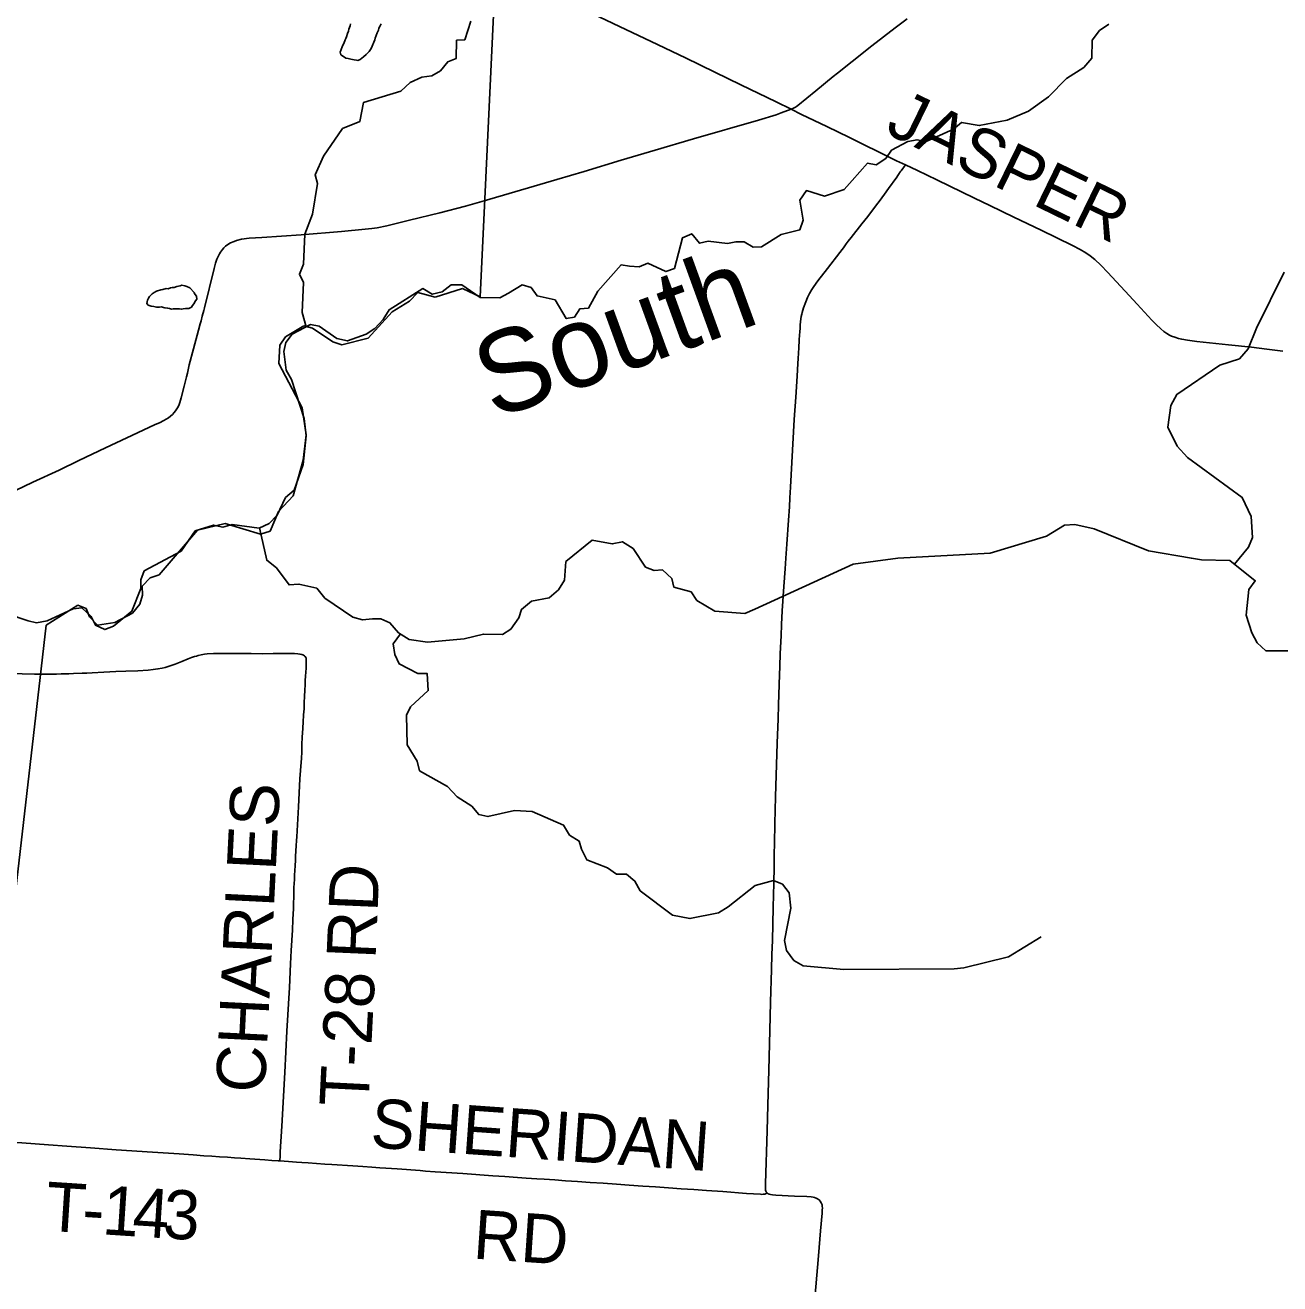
# Model space of a CAD drawing. Extents: x -49 to -8.2, y 9.4 to 23.5.
# Drawn here: x -13.706 to -12.98, y 11.259 to 11.988 of the extents above; entities that cross this region are included whole.
import ezdxf

# ---------------------------------------------------------------- set-up
doc = ezdxf.new("R2010")
doc.units = 0
for name, color, linetype in [('GM_X_County_Road', 7, 'Continuous'), ('GM_X_County_Road_Text', 7, 'Continuous'), ('GM_X_Minor_Lake', 7, 'Continuous'), ('GM_X_Minor_River', 7, 'Continuous'), ('GM_X_Minor_River_Text', 7, 'Continuous'), ('GM_X_Township', 7, 'Continuous'), ('GM_X_Township_Road', 7, 'Continuous'), ('GM_X_Township_Road_Text', 7, 'Continuous')]:
    doc.layers.add(name, color=color, linetype=linetype)

msp = doc.modelspace()

# ---------------------------------------------------------------- linework, layer by layer
at = {"layer": 'GM_X_County_Road'}
for points in [[(-13.41841, 12.01371), (-13.41025, 12.00973), (-13.40043, 12.0051), (-13.39281, 12.00159), (-13.36191, 11.98699), (-13.3437, 11.97825), (-13.32382, 11.9687), (-13.30675, 11.96046), (-13.29164, 11.95318), (-13.27121, 11.94332), (-13.26257, 11.93902)], [(-13.26257, 11.93902), (-13.26088, 11.93975), (-13.26007, 11.94021), (-13.25942, 11.94061), (-13.25876, 11.94112), (-13.24826, 11.94959), (-13.23823, 11.95794), (-13.23582, 11.9599), (-13.22726, 11.96658), (-13.21586, 11.97571), (-13.20237, 11.98618), (-13.19541, 11.99138)], [(-13.44022, 11.886), (-13.43699, 11.88691), (-13.41136, 11.89446), (-13.39827, 11.89841), (-13.38248, 11.90305), (-13.36105, 11.90947), (-13.34139, 11.91527), (-13.31905, 11.92185), (-13.28145, 11.93272), (-13.27135, 11.93587), (-13.26841, 11.93694), (-13.26257, 11.93902)], [(-13.26257, 11.93902), (-13.25657, 11.93593), (-13.24198, 11.92905), (-13.22888, 11.92263), (-13.21994, 11.91827), (-13.2124, 11.9146), (-13.20154, 11.90925), (-13.19644, 11.90684)], [(-13.27636, 11.31155), (-13.27668, 11.31183), (-13.27701, 11.31223), (-13.27729, 11.31272), (-13.27743, 11.31324), (-13.27752, 11.31393), (-13.2775, 11.31502), (-13.27743, 11.31717), (-13.27649, 11.34759), (-13.27609, 11.3625), (-13.27553, 11.38269), (-13.27494, 11.40567), (-13.27446, 11.42213), (-13.27398, 11.44107), (-13.27369, 11.44976), (-13.27344, 11.45783), (-13.27323, 11.46715), (-13.27302, 11.47709), (-13.2727, 11.49107), (-13.27248, 11.50038), (-13.27236, 11.50783), (-13.27224, 11.51404), (-13.27202, 11.52553), (-13.27162, 11.54105), (-13.27065, 11.5721), (-13.27016, 11.58607), (-13.26991, 11.59414), (-13.26949, 11.60594), (-13.26929, 11.61153), (-13.26911, 11.61649), (-13.26887, 11.62393), (-13.26845, 11.63416), (-13.26817, 11.64067), (-13.26771, 11.64873), (-13.26683, 11.66268), (-13.26604, 11.67289), (-13.26562, 11.6791), (-13.26504, 11.68715), (-13.26411, 11.70109), (-13.26363, 11.70883), (-13.26335, 11.71409), (-13.26303, 11.72029), (-13.26226, 11.73456), (-13.26076, 11.75937), (-13.25998, 11.77239), (-13.25917, 11.78448), (-13.25871, 11.79192), (-13.25853, 11.79471), (-13.25818, 11.80091), (-13.25789, 11.80524), (-13.25768, 11.80833), (-13.25759, 11.80988), (-13.25745, 11.81241), (-13.25729, 11.81421), (-13.25714, 11.81604), (-13.25695, 11.8176), (-13.25671, 11.81906), (-13.25646, 11.82048), (-13.25622, 11.82144), (-13.2559, 11.82262), (-13.25546, 11.82408), (-13.25418, 11.82754), (-13.25308, 11.83008), (-13.25199, 11.83228), (-13.25061, 11.83466), (-13.24943, 11.83644), (-13.24707, 11.83968), (-13.2416, 11.84682), (-13.23435, 11.85613), (-13.23306, 11.85786), (-13.23231, 11.85885), (-13.23066, 11.86109), (-13.22954, 11.86258), (-13.2278, 11.86476), (-13.22176, 11.87263), (-13.22, 11.8748), (-13.21828, 11.87699), (-13.2143, 11.88216), (-13.21244, 11.88464), (-13.21116, 11.8864), (-13.20768, 11.89117), (-13.20586, 11.89368), (-13.20457, 11.89542), (-13.20312, 11.89744), (-13.20184, 11.89918), (-13.20046, 11.90123), (-13.19942, 11.90274), (-13.19891, 11.90345), (-13.19644, 11.90684)], [(-13.19644, 11.90684), (-13.18947, 11.90355), (-13.1783, 11.89816), (-13.15637, 11.88749)], [(-13.72626, 11.71142), (-13.70153, 11.72307), (-13.68634, 11.73017), (-13.67485, 11.73567), (-13.65942, 11.74302), (-13.64089, 11.75176), (-13.63075, 11.75649), (-13.62819, 11.75757), (-13.62566, 11.75881), (-13.62431, 11.75961), (-13.62296, 11.76045), (-13.6218, 11.76134), (-13.62077, 11.76229), (-13.61978, 11.7634), (-13.61893, 11.76448), (-13.61813, 11.76566), (-13.61752, 11.76674), (-13.61694, 11.76809), (-13.6165, 11.76929), (-13.61562, 11.77198), (-13.61392, 11.77864), (-13.61262, 11.78408), (-13.61212, 11.78619), (-13.61098, 11.79102), (-13.60853, 11.80032), (-13.60563, 11.81111), (-13.60468, 11.81472), (-13.6042, 11.81651), (-13.60348, 11.8192), (-13.60259, 11.8225), (-13.60219, 11.824), (-13.59653, 11.84689), (-13.5958, 11.84987), (-13.59504, 11.85219), (-13.59418, 11.85413), (-13.59353, 11.85526), (-13.59292, 11.85619), (-13.59186, 11.85774), (-13.59096, 11.85876), (-13.58995, 11.85969), (-13.58815, 11.86104), (-13.58705, 11.86169), (-13.58506, 11.86254), (-13.58372, 11.86299), (-13.58075, 11.8638), (-13.57627, 11.86433), (-13.56908, 11.86479), (-13.54615, 11.86641), (-13.52295, 11.86826), (-13.50927, 11.8695), (-13.5053, 11.86997), (-13.50225, 11.87039), (-13.49674, 11.87144), (-13.4835, 11.87475), (-13.46603, 11.87904), (-13.45104, 11.88296), (-13.44022, 11.886)], [(-13.15637, 11.88749), (-13.1476, 11.88322), (-13.13362, 11.87645), (-13.11793, 11.86893), (-13.09975, 11.86011), (-13.09532, 11.85782), (-13.09208, 11.85589), (-13.08951, 11.8541), (-13.08683, 11.85194), (-13.08339, 11.84875), (-13.07925, 11.84451), (-13.06703, 11.83127), (-13.06237, 11.82626), (-13.05377, 11.81687), (-13.0514, 11.81444), (-13.04865, 11.81197), (-13.04687, 11.81042), (-13.04513, 11.80914), (-13.04362, 11.80831), (-13.04234, 11.8077), (-13.04053, 11.80702), (-13.03841, 11.80634), (-13.03647, 11.80589), (-13.03315, 11.80524), (-13.0277, 11.80453), (-13.00938, 11.80269), (-12.99609, 11.80129), (-12.98715, 11.80021), (-12.9779, 11.79897)], [(-13.24923, 11.24607), (-13.24684, 11.27518), (-13.24557, 11.28972), (-13.24464, 11.29992), (-13.24456, 11.30174), (-13.24449, 11.30294), (-13.24455, 11.30379), (-13.24473, 11.30472), (-13.24488, 11.3052), (-13.24525, 11.30601), (-13.24575, 11.30682), (-13.24645, 11.30758), (-13.24671, 11.30776), (-13.24734, 11.30818), (-13.24813, 11.30861), (-13.24902, 11.30894), (-13.24987, 11.30916), (-13.25094, 11.30936), (-13.25348, 11.30957), (-13.26065, 11.30983), (-13.27153, 11.31036), (-13.27337, 11.31054), (-13.27453, 11.31073), (-13.27535, 11.31099), (-13.27582, 11.31121), (-13.27628, 11.31148), (-13.27636, 11.31155)]]:
    msp.add_lwpolyline(points, dxfattribs=at)
at = {"layer": 'GM_X_Minor_Lake'}
for points in [[(-13.51769, 11.98838), (-13.51789, 11.98724), (-13.51828, 11.9863), (-13.51867, 11.98535), (-13.51887, 11.98422), (-13.51945, 11.98289), (-13.52004, 11.981), (-13.52043, 11.98005), (-13.52082, 11.97911), (-13.5216, 11.97703), (-13.52218, 11.97608), (-13.52257, 11.97514), (-13.52374, 11.97211), (-13.52319, 11.97059), (-13.52168, 11.96962), (-13.52036, 11.96866), (-13.51903, 11.96846), (-13.51752, 11.96806), (-13.51563, 11.96766), (-13.5143, 11.96746), (-13.51335, 11.96726), (-13.51202, 11.96781), (-13.51106, 11.96856), (-13.51011, 11.96931), (-13.50858, 11.97063), (-13.50781, 11.97157), (-13.50685, 11.97251), (-13.50569, 11.9742), (-13.50511, 11.97553), (-13.50414, 11.9778), (-13.50355, 11.97912), (-13.50335, 11.98026), (-13.50218, 11.98328), (-13.50141, 11.9848), (-13.50121, 11.98593), (-13.50043, 11.98725), (-13.49985, 11.98839)], [(-13.60812, 11.83284), (-13.61075, 11.83572), (-13.61245, 11.83631), (-13.61359, 11.8367), (-13.61529, 11.8371), (-13.61624, 11.83673), (-13.61719, 11.83655), (-13.61814, 11.83637), (-13.61967, 11.83581), (-13.62099, 11.83582), (-13.62195, 11.83564), (-13.62328, 11.83509), (-13.62442, 11.83529), (-13.62632, 11.83474), (-13.62746, 11.83456), (-13.62994, 11.83364), (-13.63127, 11.83289), (-13.63242, 11.83214), (-13.63395, 11.83064), (-13.63453, 11.8297), (-13.63511, 11.82857), (-13.63531, 11.82762), (-13.63551, 11.82648), (-13.63476, 11.82552), (-13.63306, 11.82494), (-13.63155, 11.82473), (-13.63003, 11.82452), (-13.62832, 11.82451), (-13.62718, 11.82469), (-13.6251, 11.82409), (-13.62359, 11.82389), (-13.62245, 11.82369), (-13.62132, 11.82329), (-13.62037, 11.82347), (-13.61904, 11.82346), (-13.6179, 11.82345), (-13.61657, 11.82344), (-13.61543, 11.82323), (-13.61448, 11.82341), (-13.61315, 11.82359), (-13.61125, 11.82376), (-13.60973, 11.8245), (-13.60915, 11.82545), (-13.60838, 11.82639), (-13.60741, 11.82809), (-13.60664, 11.82903), (-13.60682, 11.83074), (-13.60757, 11.8317), (-13.60812, 11.83265), (-13.60812, 11.83265), (-13.60812, 11.83284)]]:
    msp.add_lwpolyline(points, dxfattribs=at)
at = {"layer": 'GM_X_Minor_River'}
for points in [[(-13.54329, 11.8131), (-13.54574, 11.82144), (-13.5449, 11.8387), (-13.54729, 11.84348), (-13.54493, 11.84933), (-13.54409, 11.86677), (-13.53975, 11.87828), (-13.53682, 11.89608), (-13.53807, 11.90103), (-13.53336, 11.91178), (-13.5223, 11.92793), (-13.51219, 11.93195), (-13.51013, 11.94293), (-13.4886, 11.94943), (-13.48322, 11.95447), (-13.47634, 11.9576), (-13.47065, 11.95827), (-13.46567, 11.96123), (-13.46142, 11.96648), (-13.45646, 11.96849), (-13.4563, 11.97892), (-13.45155, 11.97923), (-13.44798, 11.98999)], [(-13.07867, 11.9882), (-13.08403, 11.98467), (-13.08829, 11.97904), (-13.08864, 11.96861), (-13.09327, 11.96318), (-13.10323, 11.95688), (-13.11363, 11.94622), (-13.12513, 11.93785), (-13.13753, 11.93273), (-13.1537, 11.92955), (-13.16391, 11.93142), (-13.16871, 11.9275), (-13.18436, 11.92034), (-13.18966, 11.92137), (-13.19498, 11.92031), (-13.20454, 11.91533), (-13.20784, 11.91045), (-13.21339, 11.90693), (-13.21849, 11.90776), (-13.22737, 11.89784), (-13.232, 11.8926), (-13.24324, 11.88878), (-13.25381, 11.89198), (-13.2575, 11.88634), (-13.25559, 11.87474), (-13.25757, 11.86926), (-13.26842, 11.86658), (-13.27972, 11.85935), (-13.28465, 11.85924), (-13.28972, 11.86235), (-13.29465, 11.86223), (-13.2994, 11.86136), (-13.31057, 11.86266), (-13.31571, 11.86141), (-13.32017, 11.86699), (-13.32552, 11.8646), (-13.33015, 11.84683), (-13.33511, 11.84501), (-13.34565, 11.84991), (-13.35062, 11.84771), (-13.35611, 11.84817), (-13.36102, 11.84901), (-13.37453, 11.83365), (-13.37999, 11.82387), (-13.38492, 11.82356), (-13.38803, 11.81867), (-13.39279, 11.8178), (-13.39925, 11.82871), (-13.40965, 11.83096), (-13.41318, 11.83575), (-13.41827, 11.83735), (-13.42631, 11.83254), (-13.43128, 11.82977), (-13.44265, 11.82994), (-13.45316, 11.83731)], [(-13.00599, 11.67563), (-12.99779, 11.68542), (-12.99562, 11.69108), (-12.99638, 11.70324), (-13.00152, 11.71433), (-13.03321, 11.73739), (-13.03918, 11.74393), (-13.04451, 11.75502), (-13.0428, 11.76752), (-13.03929, 11.77392), (-13.01438, 11.79081), (-13.00314, 11.79462), (-12.99812, 11.80024), (-12.9932, 11.81231), (-12.97715, 11.84471)], [(-13.45316, 11.83731), (-13.45941, 11.8374), (-13.4646, 11.83331), (-13.47031, 11.83188), (-13.47575, 11.83518), (-13.49528, 11.82296), (-13.49878, 11.81732), (-13.5036, 11.81207), (-13.50858, 11.80873), (-13.51944, 11.80491), (-13.52568, 11.80634), (-13.53581, 11.81351), (-13.54091, 11.81435), (-13.55143, 11.80882), (-13.5551, 11.80394), (-13.55632, 11.79883), (-13.55497, 11.78799), (-13.55183, 11.78263), (-13.54459, 11.75994), (-13.54342, 11.74986), (-13.545, 11.73338), (-13.55035, 11.71847), (-13.55534, 11.71418), (-13.56005, 11.704), (-13.56467, 11.69914), (-13.57059, 11.69657), (-13.5861, 11.6987), (-13.59163, 11.69708), (-13.59692, 11.6983), (-13.60758, 11.69504), (-13.61573, 11.68321), (-13.63714, 11.67177), (-13.63911, 11.66668), (-13.639, 11.66155), (-13.64432, 11.64854), (-13.65488, 11.63978), (-13.65984, 11.63777), (-13.6653, 11.64032), (-13.66788, 11.64529), (-13.67311, 11.6503), (-13.67824, 11.64981), (-13.69332, 11.64283), (-13.69941, 11.64178), (-13.70432, 11.64281), (-13.7162, 11.64697)], [(-13.57036, 11.69667), (-13.56613, 11.67791), (-13.56051, 11.67346), (-13.55327, 11.66367), (-13.54757, 11.66415), (-13.53718, 11.66172), (-13.53253, 11.65595), (-13.5164, 11.64489), (-13.51073, 11.64348), (-13.50485, 11.64396), (-13.5001, 11.64408), (-13.49483, 11.64172), (-13.4898, 11.63595), (-13.48379, 11.63206), (-13.4732, 11.63057), (-13.45194, 11.63234), (-13.44071, 11.6352), (-13.42971, 11.63485), (-13.42493, 11.638), (-13.42028, 11.64457), (-13.41868, 11.64948), (-13.41292, 11.65433), (-13.40265, 11.65626), (-13.39728, 11.66073), (-13.39378, 11.66637), (-13.39304, 11.67718), (-13.37788, 11.68948), (-13.36615, 11.6874), (-13.36026, 11.68864), (-13.35406, 11.68475), (-13.34683, 11.67401), (-13.34193, 11.67204), (-13.33699, 11.67235), (-13.33176, 11.66733), (-13.33051, 11.66238), (-13.32051, 11.65957), (-13.31717, 11.65459), (-13.30684, 11.64836), (-13.28941, 11.64714), (-13.28369, 11.64953), (-13.22679, 11.67561), (-13.20076, 11.6792), (-13.14744, 11.682), (-13.11487, 11.69194), (-13.10434, 11.69824), (-13.09846, 11.69853), (-13.08712, 11.69608), (-13.05565, 11.68345), (-13.03088, 11.67909), (-13.02502, 11.67825), (-13.00872, 11.67781), (-12.99392, 11.66601), (-12.9976, 11.66094), (-12.99915, 11.64616), (-12.9959, 11.63587), (-12.99276, 11.63012), (-12.9879, 11.6255), (-12.97217, 11.62545)], [(-13.4887, 11.63524), (-13.49293, 11.62954), (-13.49208, 11.62327), (-13.48951, 11.61792), (-13.47878, 11.61244), (-13.47329, 11.61236), (-13.47268, 11.60248), (-13.48287, 11.59314), (-13.48522, 11.58825), (-13.48491, 11.57116), (-13.47899, 11.56158), (-13.47775, 11.55606), (-13.46159, 11.5469), (-13.45585, 11.541)], [(-13.45585, 11.541), (-13.44752, 11.53549), (-13.4434, 11.5307), (-13.43811, 11.52949), (-13.4227, 11.53309), (-13.41247, 11.53238), (-13.39436, 11.52456), (-13.39082, 11.51882), (-13.38537, 11.51533), (-13.3839, 11.51057), (-13.38094, 11.50446), (-13.36886, 11.49993), (-13.36378, 11.49626), (-13.3579, 11.49619), (-13.35302, 11.49214), (-13.35005, 11.48659), (-13.33126, 11.47249), (-13.32123, 11.47047), (-13.30469, 11.47386), (-13.29915, 11.4772), (-13.28345, 11.48972), (-13.27279, 11.49262), (-13.2677, 11.49046), (-13.26377, 11.48548), (-13.26274, 11.47654), (-13.26638, 11.4578), (-13.26531, 11.45209), (-13.26102, 11.44615), (-13.25556, 11.44305), (-13.23206, 11.44103), (-13.16833, 11.44135), (-13.16264, 11.44203), (-13.13677, 11.44834), (-13.11785, 11.45987)]]:
    msp.add_lwpolyline(points, dxfattribs=at)
at = {"layer": 'GM_X_Township'}
for p, q in [((-13.43999, 11.88719), (-13.43497, 11.99346)), ((-13.44267, 11.83046), (-13.43999, 11.88719)), ((-13.46866, 11.83021), (-13.45285, 11.83533)), ((-13.45285, 11.83533), (-13.44267, 11.83046)), ((-13.49362, 11.82179), (-13.48349, 11.82793)), ((-13.48349, 11.82793), (-13.47869, 11.833)), ((-13.47869, 11.833), (-13.46866, 11.83021)), ((-13.50747, 11.80658), (-13.49362, 11.82179)), ((-13.55527, 11.80736), (-13.54476, 11.81369)), ((-13.54476, 11.81369), (-13.53966, 11.8123)), ((-13.53966, 11.8123), (-13.52799, 11.80437)), ((-13.55856, 11.80247), (-13.55527, 11.80736)), ((-13.52799, 11.80437), (-13.5227, 11.80259)), ((-13.5227, 11.80259), (-13.50747, 11.80658)), ((-13.55907, 11.79184), (-13.55856, 11.80247)), ((-13.54572, 11.76623), (-13.55907, 11.79184)), ((-13.54326, 11.75045), (-13.54572, 11.76623)), ((-13.54515, 11.73585), (-13.54326, 11.75045)), ((-13.55091, 11.71522), (-13.54515, 11.73585)), ((-13.55936, 11.70622), (-13.55091, 11.71522)), ((-13.56425, 11.69469), (-13.55936, 11.70622)), ((-13.6285, 11.66948), (-13.60617, 11.6954)), ((-13.60617, 11.6954), (-13.59019, 11.69919)), ((-13.59019, 11.69919), (-13.56977, 11.69305)), ((-13.56977, 11.69305), (-13.56425, 11.69469)), ((-13.63826, 11.66295), (-13.63364, 11.66783)), ((-13.63364, 11.66783), (-13.6285, 11.66948)), ((-13.63813, 11.65764), (-13.63826, 11.66295)), ((-13.69394, 11.64029), (-13.67558, 11.65184)), ((-13.67558, 11.65184), (-13.67067, 11.65007)), ((-13.64395, 11.64727), (-13.63971, 11.65253)), ((-13.63971, 11.65253), (-13.63813, 11.65764)), ((-13.67067, 11.65007), (-13.66883, 11.64511)), ((-13.66883, 11.64511), (-13.66415, 11.6403)), ((-13.65407, 11.64189), (-13.64395, 11.64727)), ((-13.69741, 11.61008), (-13.69394, 11.64029)), ((-13.66415, 11.6403), (-13.65407, 11.64189)), ((-13.72879, 11.33712), (-13.69741, 11.61008))]:
    msp.add_line(p, q, dxfattribs=at)
at = {"layer": 'GM_X_Township_Road'}
for points in [[(-13.54327, 11.61709), (-13.54335, 11.61976), (-13.54339, 11.62085), (-13.54343, 11.62121), (-13.54357, 11.62162), (-13.54397, 11.62224), (-13.5444, 11.62268), (-13.54492, 11.623), (-13.54532, 11.62322), (-13.54578, 11.62336), (-13.547, 11.62362), (-13.54813, 11.62377), (-13.55009, 11.62391), (-13.55331, 11.62399), (-13.55846, 11.62395), (-13.56243, 11.62399), (-13.56842, 11.62384), (-13.57509, 11.62388), (-13.58349, 11.62395), (-13.58779, 11.62391), (-13.59093, 11.62391), (-13.59691, 11.62395), (-13.6007, 11.62377), (-13.60216, 11.62355), (-13.60407, 11.62314), (-13.60586, 11.6227), (-13.60676, 11.62246), (-13.60796, 11.62213), (-13.60972, 11.62158), (-13.61165, 11.62085), (-13.6153, 11.61939), (-13.6172, 11.61859), (-13.61918, 11.61782), (-13.62153, 11.61701), (-13.62325, 11.6164), (-13.625, 11.61585), (-13.62664, 11.61545), (-13.6292, 11.61498), (-13.63183, 11.61465), (-13.63471, 11.61436), (-13.64069, 11.61396), (-13.64773, 11.6137), (-13.6535, 11.61344), (-13.66046, 11.61308), (-13.66715, 11.61276), (-13.67025, 11.61261), (-13.67303, 11.61249), (-13.67802, 11.61235), (-13.68082, 11.61223), (-13.68325, 11.61218), (-13.68513, 11.61213), (-13.68783, 11.61202), (-13.69148, 11.61198)], [(-13.5585, 11.33015), (-13.55841, 11.33322), (-13.55835, 11.33539), (-13.55752, 11.35029), (-13.55578, 11.38133), (-13.55445, 11.40522), (-13.55305, 11.43067), (-13.55238, 11.44434), (-13.55193, 11.45209), (-13.55134, 11.46382), (-13.55105, 11.46992), (-13.55076, 11.4763), (-13.55052, 11.48592), (-13.55041, 11.4884), (-13.55018, 11.49306), (-13.55003, 11.49553), (-13.54972, 11.50111), (-13.54953, 11.50421), (-13.54942, 11.50669), (-13.54912, 11.51258), (-13.54893, 11.51568), (-13.54882, 11.51785), (-13.54777, 11.53523), (-13.54692, 11.55137), (-13.54618, 11.56097), (-13.54604, 11.56314), (-13.54599, 11.56438), (-13.54587, 11.56593), (-13.54589, 11.56686), (-13.54587, 11.56871), (-13.54585, 11.56995), (-13.54582, 11.57026), (-13.54579, 11.57088), (-13.54559, 11.57583), (-13.54547, 11.57765), (-13.54507, 11.58415), (-13.54481, 11.58838), (-13.54459, 11.59181), (-13.54448, 11.59564), (-13.5443, 11.59911), (-13.54408, 11.60275), (-13.54397, 11.60586), (-13.54388, 11.60838), (-13.54372, 11.61085), (-13.54343, 11.61538), (-13.54327, 11.61709)], [(-13.69148, 11.61198), (-13.69261, 11.61197), (-13.69505, 11.61195), (-13.70063, 11.61202), (-13.70778, 11.61225), (-13.71365, 11.61254), (-13.71986, 11.61278), (-13.72575, 11.61295), (-13.72745, 11.61297), (-13.7292, 11.61301), (-13.73161, 11.61301), (-13.73427, 11.61301), (-13.7365, 11.61297), (-13.73901, 11.61297), (-13.74131, 11.61297)], [(-13.726, 11.34085), (-13.72365, 11.34113), (-13.72238, 11.34127), (-13.72085, 11.34135), (-13.71688, 11.34119), (-13.70789, 11.34061), (-13.69253, 11.33945), (-13.68187, 11.33869), (-13.66824, 11.33769), (-13.65337, 11.33662), (-13.63229, 11.33531), (-13.61679, 11.33419), (-13.60874, 11.33362), (-13.60254, 11.33321), (-13.59789, 11.33295), (-13.59355, 11.33261), (-13.5889, 11.33231), (-13.58487, 11.332), (-13.58116, 11.33174), (-13.57589, 11.33137), (-13.56732, 11.33077), (-13.56313, 11.33044), (-13.55947, 11.33021), (-13.5585, 11.33015)], [(-13.5585, 11.33015), (-13.55606, 11.33), (-13.55359, 11.32984), (-13.54893, 11.32954), (-13.54584, 11.32932), (-13.54212, 11.32907), (-13.53252, 11.3284), (-13.52848, 11.32815), (-13.5164, 11.32731), (-13.51053, 11.32689), (-13.50527, 11.32652), (-13.50063, 11.32619), (-13.49723, 11.32596), (-13.49072, 11.32555), (-13.4774, 11.32459), (-13.4743, 11.32431), (-13.46873, 11.32391), (-13.45269, 11.32281), (-13.43525, 11.32157), (-13.42832, 11.32114), (-13.421, 11.32062), (-13.41605, 11.32026), (-13.40985, 11.31983), (-13.40551, 11.31958), (-13.39932, 11.31916), (-13.39313, 11.31873), (-13.38632, 11.31825), (-13.37889, 11.31775), (-13.37145, 11.31723), (-13.36371, 11.31673), (-13.3563, 11.31617), (-13.34854, 11.31564), (-13.34111, 11.3151), (-13.33367, 11.31457), (-13.32624, 11.3141), (-13.31887, 11.31358), (-13.31153, 11.31307), (-13.30208, 11.31242), (-13.28845, 11.31141), (-13.28038, 11.31084), (-13.27965, 11.31081), (-13.27885, 11.31085), (-13.2779, 11.311), (-13.27699, 11.31129), (-13.27636, 11.31155)]]:
    msp.add_lwpolyline(points, dxfattribs=at)

# ---------------------------------------------------------------- texts
at = {"layer": 'GM_X_County_Road_Text'}
msp.add_text('JASPER', height=0.028409, rotation=334.03993, dxfattribs=at).set_placement((-13.20901, 11.9257))
at = {"layer": 'GM_X_Minor_River_Text'}
msp.add_text('South', height=0.047346, rotation=19.99901, dxfattribs=at).set_placement((-13.43483, 11.75918))
at = {"layer": 'GM_X_Township_Road_Text'}
for s, height, rotation, p in [('CHARLES', 0.028409, 87.16632, (-13.56732, 11.36921)), ('RD', 0.028409, 87.5301, (-13.5032, 11.44671)), ('T-28', 0.028409, 87.15552, (-13.50733, 11.36121)), ('SHERIDAN', 0.028409, 355.9622, (-13.50659, 11.33813)), ('T', 0.02841, 356.26461, (-13.69479, 11.28987)), ('1', 0.02841, 356.29775, (-13.66192, 11.28772)), ('4', 0.02841, 356.36505, (-13.64442, 11.28659)), ('3', 0.02841, 356.67052, (-13.62679, 11.28547)), ('RD', 0.028409, 356.12559, (-13.44722, 11.2737)), ('-', 0.02841, 356.2649, (-13.67358, 11.28848))]:
    msp.add_text(s, height=height, rotation=rotation, dxfattribs=at).set_placement(p)

doc.saveas('drawing.dxf')
